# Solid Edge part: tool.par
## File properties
Author: Romil
Template: Iso Part.par
Last saved by: Romil
Revision: 19
Application: Solid Edge
Accuracy: 0.990
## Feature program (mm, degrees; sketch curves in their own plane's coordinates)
sketch for "unnamed Protrusion 1" plane through (0, 0, 0) normal (0, 0, 1) x-axis (1, 0, 0)
  line (23.8, 7.9) -> (23.8, -7.9)
  line (23.8, -7.9) -> (0, -7.9)
  line (0, -7.9) -> (0, 7.9)
  line (0, 7.9) -> (23.8, 7.9)
extrude "unnamed Protrusion 1" add finite 18.2 along +normal
sketch for "ExtrudedProtrusion_2" plane through (0, 0, 0) normal (0, -1, 0) x-axis (1, 0, 0)
  line (-1.8655, 31.7221) -> (-0.9815, 27.8216)
  arc centre (-0.884, 27.8437) radius 0.1 from (-0.9815, 27.8216) to (-0.963, 27.7825) ccw
  line (-0.963, 27.7825) -> (8.4676, 15.6125)
  arc centre (7.6771, 15) radius 1 from (7.6771, 14) to (8.4676, 15.6125) ccw
  line (7.6771, 14) -> (2.1511, 14)
  line (2.1511, 14) -> (2.5591, 12.2)
  line (11.5232, 12.2) -> (2.5591, 12.2)
  line (11.5232, 12.2) -> (20.6599, 12.2)
  arc centre (20.6599, 10.7) radius 1.5 from (20.6599, 12.2) to (22.1051, 11.1015) cw
  line (23.8, 5) -> (22.1051, 11.1015)
  line (23.8, 1.8) -> (23.8, 5)
  line (3.7179, 1.8) -> (23.8, 1.8)
  line (3.7179, 1.8) -> (-3.0555, 31.6779)
  arc centre (-2.958, 31.7) radius 0.1 from (-3.0555, 31.6779) to (-2.958, 31.8) cw
  line (-2.958, 31.8) -> (-1.963, 31.8)
  arc centre (-1.963, 31.7) radius 0.1 from (-1.8655, 31.7221) to (-1.963, 31.8) ccw
extrude "ExtrudedProtrusion_2" add finite 31.8 symmetric
sketch for "ExtrudedCutout_1" #1 plane through (0, 0, 0) normal (1, 0, 0) x-axis (0, 1, 0)
  line (-22.2684, 12.2) -> (-22.2684, 36.765)
  line (-22.2684, 36.765) -> (-15.9, 36.198)
  line (-15.9, 36.198) -> (-9.2, 36.198)
  line (-9.2, 36.198) -> (-9.2, 12.2)
  line (-9.2, 12.2) -> (-22.2684, 12.2)
sketch for "ExtrudedCutout_1" #2 plane through (0, 0, 0) normal (1, 0, 0) x-axis (0, 1, 0)
  line (15.9, 36.198) -> (9.2, 36.198)
  line (9.2, 36.198) -> (9.2, 12.2)
  line (9.2, 12.2) -> (22.2684, 12.2)
  line (22.2684, 12.2) -> (22.2684, 36.765)
  line (22.2684, 36.765) -> (15.9, 36.198)
extrude "ExtrudedCutout_1" cut finite 113.7012 symmetric
sketch for "unnamed Cutout 1" plane through (0, -35.2373, 0) normal (0, -1, 0) x-axis (1, 0, 0)
  line (0, 0) -> (0, 0)
  line (-0.963, 27.7825) -> (20.7421, 27.7825)
  line (20.7421, 27.7825) -> (26.4702, 27.7825)
  line (26.4702, 27.7825) -> (25.9334, 3)
  line (6.641, 3) -> (25.9334, 3)
  arc centre (6.641, 5.5) radius 2.5 from (4.2028, 4.9474) to (6.641, 3) ccw
  line (2.1511, 14) -> (4.2028, 4.9474)
  line (2.1511, 14) -> (7.6771, 14)
  arc centre (7.6771, 15) radius 1 from (7.6771, 14) to (8.4676, 15.6125) ccw
  line (-0.963, 27.7825) -> (8.4676, 15.6125)
extrude "unnamed Cutout 1" cut along -normal
sketch for "unnamed Cutout 2" plane through (0, -35.2373, 0) normal (0, -1, 0) x-axis (1, 0, 0)
  line (11.8926, 5.5) -> (6.5536, 5.5)
  arc centre (6.5536, 8.6) radius 3.1 from (6.5536, 5.5) to (3.5303, 7.9148) cw
  line (2.1511, 14) -> (3.5303, 7.9148)
  line (2.1511, 14) -> (7.6771, 14)
  line (10.977, 14) -> (7.6771, 14)
  line (17.8766, 15.3192) -> (10.977, 14)
  line (17.8766, 5.5) -> (17.8766, 15.3192)
  line (11.8926, 5.5) -> (17.8766, 5.5)
extrude "unnamed Cutout 2" cut along -normal
sketch for "unnamed Cutout 3" plane through (0, -35.2373, 0) normal (0, -1, 0) x-axis (1, 0, 0)
  line (17.8766, 5.5) -> (17.8766, 15.3192)
  line (17.8766, 15.3192) -> (10.977, 14)
  line (10.977, 14) -> (7.6771, 14)
  line (2.1511, 14) -> (7.6771, 14)
  line (2.1511, 14) -> (3.5303, 7.9148)
  arc centre (6.5536, 8.6) radius 3.1 from (6.5536, 5.5) to (3.5303, 7.9148) cw
  line (11.8926, 5.5) -> (6.5536, 5.5)
  line (11.8926, 5.5) -> (17.8766, 5.5)
extrude "unnamed Cutout 3" cut along -normal
sketch for "unnamed Cutout 4" plane through (0, -35.2373, 0) normal (0, -1, 0) x-axis (1, 0, 0)
  line (-0.3297, 5) -> (-0.3297, 0)
  line (-0.3297, 0) -> (26.2671, 0)
  line (26.2671, 0) -> (26.2671, 5)
  line (7.3837, 5) -> (26.2671, 5)
  line (7.3837, 5) -> (-0.3297, 5)
extrude "unnamed Cutout 4" cut along -normal
sketch for "unnamed Cutout 5" plane through (0, -35.2373, 0) normal (0, -1, 0) x-axis (1, 0, 0)
  line (7.3837, 5) -> (-0.3297, 5)
  line (-0.3297, 5) -> (-0.3297, 0)
  line (-0.3297, 0) -> (26.2671, 0)
  line (26.2671, 0) -> (26.2671, 5)
  line (7.3837, 5) -> (26.2671, 5)
extrude "unnamed Cutout 5" cut along -normal
sketch for "unnamed Cutout 6" plane through (0, 0, 0) normal (1, 0, 0) x-axis (0, 1, 0)
  line (8.6, 29.1117) -> (-8.6, 29.1117)
  line (-8.6, 29.1117) -> (-8.6, 9.0802)
  line (-8.6, 9.0802) -> (8.6, 9.0802)
  line (8.6, 9.0802) -> (8.6, 29.1117)
extrude "unnamed Cutout 6" cut along +normal
sketch for "ExtrudedCutout_19" #1 plane through (0, 0, 0) normal (0, -1, 0) x-axis (1, 0, 0)
  circle centre (14.5536, 8.6) radius 2.4
sketch for "ExtrudedCutout_19" #2 plane through (0, 0, 0) normal (0, -1, 0) x-axis (1, 0, 0)
  circle centre (6.5536, 8.6) radius 2.4
extrude "ExtrudedCutout_19" cut finite 58.1345 symmetric
fillet "Round_1" radius 0.9
sketch for "ExtrudedCutout_20" #1 plane through (12.5801, -15.9, 8.6) normal (0, -1, 0) x-axis (1, 0, 0)
  circle centre (1.9735, 0) radius 3.1
sketch for "ExtrudedCutout_20" #2 plane through (12.5801, -15.9, 8.6) normal (0, -1, 0) x-axis (1, 0, 0)
  circle centre (-6.0265, 0) radius 3.1
extrude "ExtrudedCutout_20" cut finite 0.9 along -normal
sketch for "unnamed Cutout 7" plane through (-13.9505, 0, 0) normal (1, 0, 0) x-axis (0, 1, 0)
  line (-6.7, 12.4028) -> (-6.7, 17)
  line (-6.7, 17) -> (-4.9951, 17)
  line (5.4564, 17) -> (-4.9951, 17)
  line (6.7, 17) -> (5.4564, 17)
  line (6.7, 12.4028) -> (6.7, 17)
  line (6.7, 12.4028) -> (6.7, 7.9566)
  line (6.7, 7.9566) -> (6.7, 5)
  line (6.7, 3.8) -> (6.7, 5)
  line (4.455, 3.8) -> (6.7, 3.8)
  line (4.455, 4.4) -> (4.455, 3.8)
  line (4.455, 4.4) -> (4.455, 5)
  line (4.455, 5) -> (3.255, 5)
  line (3.255, 5) -> (3.255, 3.8)
  line (3.255, 3.8) -> (-3.255, 3.8)
  line (-3.255, 5) -> (-3.255, 3.8)
  line (-3.255, 5) -> (-4.455, 5)
  line (-4.455, 4.4) -> (-4.455, 5)
  line (-4.455, 4.4) -> (-4.455, 3.8)
  line (-4.455, 3.8) -> (-6.7, 3.8)
  line (-6.7, 3.8) -> (-6.7, 5)
  line (-6.7, 12.4028) -> (-6.7, 5)
extrude "unnamed Cutout 7" cut along +normal
logasc func "Lip_Groove_4"  LipOrGrooveWidth = 1 mm; LipOrGrooveHeight = 1 mm
logasc func "Lip_Groove_5"  LipOrGrooveWidth = 1 mm; LipOrGrooveHeight = 2 mm
logasc func "Lip_Groove_6"  LipOrGrooveWidth = 1 mm; LipOrGrooveHeight = 1 mm
logasc func "Lip_Groove_7"  LipOrGrooveWidth = 1 mm; LipOrGrooveHeight = 1 mm
logasc func "Lip_Groove_8"  LipOrGrooveWidth = 1 mm; LipOrGrooveHeight = 1 mm
mirror "unnamed Mirror 1" of "ExtrudedCutout_20", "Lip_Groove_4", "Lip_Groove_7", "Lip_Groove_6" about plane through (0, 0, 0) normal (0, -1, 0)
extrude "unnamed Cutout 8" cut finite 0.9
logasc func "unnamed LOGAscFunc 1"
logasc func "unnamed LOGAscFunc 2"
logasc func "unnamed LOGAscFunc 3"
logasc func "Lip_Groove_17"  LipOrGrooveWidth = 1 mm; LipOrGrooveHeight = 2 mm
logasc func "Lip_Groove_18"  LipOrGrooveWidth = 1 mm; LipOrGrooveHeight = 1 mm
sketch for "ExtrudedCutout_22" plane through (11.9, 0, 0) normal (0, 0, -1) x-axis (0, -1, 0)
  line (-7.3, 11.3) -> (-7.3, -11.3)
  line (-7.3, -11.3) -> (7.3, -11.3)
  line (7.3, -11.3) -> (7.3, 11.3)
  line (7.3, 11.3) -> (-7.3, 11.3)
extrude "ExtrudedCutout_22" cut finite 2 along -normal
sketch for "unnamed Protrusion 2" #1 plane through (11.9, 0, 0) normal (0, 0, -1) x-axis (0, -1, 0)
  circle centre (0, 4) radius 3.255
sketch for "unnamed Protrusion 2" #2 plane through (11.9, 0, 0) normal (0, 0, -1) x-axis (0, -1, 0)
  circle centre (0, -4) radius 3.255
extrude "unnamed Protrusion 2" add to key point along -normal
sketch for "unnamed Cutout 9" #1 plane through (11.9, 0, 0) normal (0, 0, -1) x-axis (0, -1, 0)
  circle centre (0, 4) radius 2.4
sketch for "unnamed Cutout 9" #2 plane through (11.9, 0, 0) normal (0, 0, -1) x-axis (0, -1, 0)
  circle centre (0, -4) radius 2.4
extrude "unnamed Cutout 9" cut to key point along -normal
sketch for "unnamed Protrusion 3" plane through (-13.9505, 0, 0) normal (1, 0, 0) x-axis (0, 1, 0)
  circle centre (0, 11) radius 3.255
extrude "unnamed Protrusion 3" add along +normal
sketch for "unnamed Cutout 10" plane through (-13.9505, 0, 0) normal (1, 0, 0) x-axis (0, 1, 0)
  circle centre (0, 11) radius 2.4
extrude "unnamed Cutout 10" cut along +normal
Other named dimensions: "ExtrudedSurface_2": FiniteDepth = 91.0685 mm | "ExtrudedSurface_3": FiniteDepth = 436.5734 mm | "ExtrudedSurface_6": FiniteDepth = 1375.4947 mm | "ExtrudedSurface_7": FiniteDepth = 1208.2439 mm | "OffsetSurface_2": Distance = 1.2 mm | "OffsetSurface_3": Distance = 1.2 mm | "ExtrudedSurface_8": FiniteDepth = 76.2865 mm | "ExtrudedSurface_9": FiniteDepth = 140.5724 mm
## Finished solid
Body 1: sheet body, 5 faces, 16 edges, 12 vertices.
  Faces by surface: plane 4, cylinder 1
  Edges by curve: line 14, circle 2
Body 2: sheet body, 1 face, 4 edges, 4 vertices.
  Faces by surface: plane 1
  Edges by curve: line 4
Body 3: sheet body, 3 faces, 10 edges, 8 vertices.
  Faces by surface: plane 2, cylinder 1
  Edges by curve: line 8, circle 2
Body 4: sheet body, 3 faces, 10 edges, 8 vertices.
  Faces by surface: plane 2, cylinder 1
  Edges by curve: line 8, circle 2
Body 5: sheet body, 3 faces, 10 edges, 8 vertices.
  Faces by surface: plane 2, cylinder 1
  Edges by curve: line 8, circle 2
Body 6: sheet body, 3 faces, 10 edges, 8 vertices.
  Faces by surface: plane 2, cylinder 1
  Edges by curve: line 8, circle 2
Body 7: sheet body, 3 faces, 10 edges, 8 vertices.
  Faces by surface: plane 2, cylinder 1
  Edges by curve: line 8, circle 2
Body 8: sheet body, 3 faces, 10 edges, 8 vertices.
  Faces by surface: plane 2, cylinder 1
  Edges by curve: line 8, circle 2
Body 9: solid body, 137 faces, 341 edges, 204 vertices.
  Faces by surface: plane 93, cylinder 38, blend 2, sphere 2, torus 2
  Edges by curve: line 243, circle 76, ellipse 14, intersection 8
Bounding box of the edges (mm; curved faces can reach further): 54.570 x 140.572 x 1375.495, from (-19.3884, -70.2862, -687.7474) to (35.1817, 70.2862, 687.7474).
Cylindrical faces by radius (mm): R0.1 x4, R0.2 x4, R0.9 x4, R1 x2, R1.5 x2, R2.4 x7, R2.5 x5, R3.1 x6, R3.255 x3, R71.1117 x4, R72.3117 x4
Toroidal faces (ring radius, tube radius in mm): R72.0117 r0.9 x2
Spherical faces by radius (mm): R0.9 x2
Planar faces by outward normal: +x 2, +y 17, +z 15, -x 4, -y 18, -z 19, oblique 18
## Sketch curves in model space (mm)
line (25.3334, 0, 3) -> (25.3334, 0, -11.652)
line (1.1859, 0, 33.233) -> (1.1859, 0, 15.6113)
line (1.1859, 0, 15.6113) -> (3.6028, 0, 4.9474)
arc centre (6.041, 0, 5.5) radius 2.5 from (3.6028, 0, 4.9474) through (4.5387, 0, 3.5017) to (6.041, 0, 3)
line (6.041, 0, 3) -> (25.3334, 0, 3)
circle centre (-13.9505, 0, 11) radius 3.255
circle centre (-13.9505, 0, 11) radius 2.4
line (-13.9505, -6.7, 17) -> (-13.9505, -4.9951, 17)
line (-13.9505, -6.7, 12.4028) -> (-13.9505, -6.7, 17)
line (-13.9505, -6.7, 12.4028) -> (-13.9505, -6.7, 5)
line (-13.9505, -6.7, 3.8) -> (-13.9505, -6.7, 5)
line (-13.9505, -4.455, 3.8) -> (-13.9505, -6.7, 3.8)
line (-13.9505, -4.455, 4.4) -> (-13.9505, -4.455, 3.8)
line (-13.9505, -4.455, 4.4) -> (-13.9505, -4.455, 5)
line (-13.9505, -3.255, 5) -> (-13.9505, -4.455, 5)
line (-13.9505, -3.255, 5) -> (-13.9505, -3.255, 3.8)
line (-13.9505, 3.255, 3.8) -> (-13.9505, -3.255, 3.8)
line (-13.9505, 3.255, 5) -> (-13.9505, 3.255, 3.8)
line (-13.9505, 4.455, 5) -> (-13.9505, 3.255, 5)
line (-13.9505, 4.455, 4.4) -> (-13.9505, 4.455, 5)
line (-13.9505, 4.455, 4.4) -> (-13.9505, 4.455, 3.8)
line (-13.9505, 4.455, 3.8) -> (-13.9505, 6.7, 3.8)
line (-13.9505, 6.7, 3.8) -> (-13.9505, 6.7, 5)
line (-13.9505, 6.7, 7.9566) -> (-13.9505, 6.7, 5)
line (-13.9505, 6.7, 12.4028) -> (-13.9505, 6.7, 7.9566)
line (-13.9505, 6.7, 12.4028) -> (-13.9505, 6.7, 17)
line (-13.9505, 6.7, 17) -> (-13.9505, 5.4564, 17)
line (-13.9505, 5.4564, 17) -> (-13.9505, -4.9951, 17)
circle centre (7.9, 0, 0) radius 3.255
circle centre (15.9, 0, 0) radius 3.255
circle centre (15.9, 0, 0) radius 2.4
circle centre (7.9, 0, 0) radius 2.4
line (23.2, -7.3, 0) -> (0.6, -7.3, 0)
line (0.6, -7.3, 0) -> (0.6, 7.3, 0)
line (0.6, 7.3, 0) -> (23.2, 7.3, 0)
line (23.2, 7.3, 0) -> (23.2, -7.3, 0)
circle centre (14.5536, -15.9, 8.6) radius 3.1
circle centre (6.5536, -15.9, 8.6) radius 3.1
circle centre (14.5536, 0, 8.6) radius 3.1
circle centre (14.5536, 0, 8.6) radius 2.4
circle centre (6.5536, 0, 8.6) radius 2.4
circle centre (6.5536, 0, 8.6) radius 3.1
circle centre (6.5536, 0, 8.6) radius 3.1
line (0, 8.6, 9.0802) -> (0, 8.6, 29.1117)
line (0, 8.6, 29.1117) -> (0, -8.6, 29.1117)
line (0, -8.6, 29.1117) -> (0, -8.6, 9.0802)
line (0, -8.6, 9.0802) -> (0, 8.6, 9.0802)
line (-2.0802, 0, 32.6694) -> (6.7206, 0, -6.1618)
line (17.8766, -35.2373, 5.5) -> (17.8766, -35.2373, 15.3192)
line (17.8766, -35.2373, 15.3192) -> (10.977, -35.2373, 14)
line (10.977, -35.2373, 14) -> (7.6771, -35.2373, 14)
line (2.1511, -35.2373, 14) -> (7.6771, -35.2373, 14)
line (2.1511, -35.2373, 14) -> (3.5303, -35.2373, 7.9148)
arc centre (6.5536, -35.2373, 8.6) radius 3.1 from (6.5536, -35.2373, 5.5) through (4.5488, -35.2373, 6.2355) to (3.5303, -35.2373, 7.9148)
line (11.8926, -35.2373, 5.5) -> (6.5536, -35.2373, 5.5)
line (11.8926, -35.2373, 5.5) -> (17.8766, -35.2373, 5.5)
arc centre (7.6771, -35.2373, 15) radius 1 from (7.6771, -35.2373, 14) through (8.575, -35.2373, 14.5598) to (8.4676, -35.2373, 15.6125)
line (2.1511, -35.2373, 14) -> (7.6771, -35.2373, 14)
line (2.1511, -35.2373, 14) -> (4.2028, -35.2373, 4.9474)
arc centre (6.641, -35.2373, 5.5) radius 2.5 from (4.2028, -35.2373, 4.9474) through (5.1387, -35.2373, 3.5017) to (6.641, -35.2373, 3)
line (6.641, -35.2373, 3) -> (25.9334, -35.2373, 3)
line (26.4702, -35.2373, 27.7825) -> (25.9334, -35.2373, 3)
line (20.7421, -35.2373, 27.7825) -> (26.4702, -35.2373, 27.7825)
line (-0.963, -35.2373, 27.7825) -> (20.7421, -35.2373, 27.7825)
line (-0.963, -35.2373, 27.7825) -> (8.4676, -35.2373, 15.6125)
line (0, 7.9, 0) -> (-19.3884, 7.9, 0)
arc centre (0, 80.2117, 0) radius 72.3117 from (0, 7.9, 0) through (6.0339, 8.1522, 0) to (12.0257, 8.907, 0)
line (35.1817, 15.1866, 0) -> (12.0257, 8.907, 0)
line (0, -7.9, 0) -> (-17.2765, -7.9, 0)
arc centre (0, -80.2117, 0) radius 72.3117 from (0, -7.9, 0) through (6.0339, -8.1522, 0) to (12.0257, -8.907, 0)
line (35.1817, -15.1866, 0) -> (12.0257, -8.907, 0)
line (26.2671, -35.2373, 0) -> (26.2671, -35.2373, 5)
line (-0.3297, -35.2373, 0) -> (26.2671, -35.2373, 0)
line (-0.3297, -35.2373, 5) -> (-0.3297, -35.2373, 0)
line (7.3837, -35.2373, 5) -> (-0.3297, -35.2373, 5)
line (7.3837, -35.2373, 5) -> (26.2671, -35.2373, 5)
arc centre (6.641, -35.2373, 5.5) radius 2.5 from (4.2028, -35.2373, 4.9474) through (5.1387, -35.2373, 3.5017) to (6.641, -35.2373, 3)
line (6.641, -35.2373, 3) -> (25.9334, -35.2373, 3)
line (26.4702, -35.2373, 27.7825) -> (25.9334, -35.2373, 3)
line (20.7421, -35.2373, 27.7825) -> (26.4702, -35.2373, 27.7825)
line (-0.963, -35.2373, 27.7825) -> (20.7421, -35.2373, 27.7825)
line (-0.963, -35.2373, 27.7825) -> (8.4676, -35.2373, 15.6125)
arc centre (7.6771, -35.2373, 15) radius 1 from (7.6771, -35.2373, 14) through (8.575, -35.2373, 14.5598) to (8.4676, -35.2373, 15.6125)
line (2.1511, -35.2373, 14) -> (7.6771, -35.2373, 14)
line (2.1511, -35.2373, 14) -> (4.2028, -35.2373, 4.9474)
arc centre (6.5536, -35.2373, 8.6) radius 3.1 from (6.5536, -35.2373, 5.5) through (4.5488, -35.2373, 6.2355) to (3.5303, -35.2373, 7.9148)
line (11.8926, -35.2373, 5.5) -> (25.9876, -35.2373, 5.5)
line (11.8926, -35.2373, 5.5) -> (6.5536, -35.2373, 5.5)
arc centre (23.6, -12.253, 0) radius 0.2 from (23.8, -12.253, 0) through (23.7589, -12.1315, 0) to (23.6523, -12.06, 0)
line (35.1817, -15.1866, 0) -> (12.0257, -8.907, 0)
arc centre (11.9734, -9.1, 0) radius 0.2 from (11.9734, -8.9, 0) through (11.9998, -8.9018, 0) to (12.0257, -8.907, 0)
line (8, -8.9, 0) -> (11.9734, -8.9, 0)
line (0, -8.9, 0) -> (-16.7142, -8.9, 0)
line (0, -8.9, 0) -> (8, -8.9, 0)
line (35.1817, 15.1866, 0) -> (12.0257, 8.907, 0)
arc centre (11.9734, 9.1, 0) radius 0.2 from (11.9734, 8.9, 0) through (11.9998, 8.9018, 0) to (12.0257, 8.907, 0)
line (8, 8.9, 0) -> (11.9734, 8.9, 0)
line (0, 8.9, 0) -> (-16.7142, 8.9, 0)
line (0, 8.9, 0) -> (8, 8.9, 0)
line (0, -9.2, 31.8637) -> (0, 9.2, 31.8637)
line (0, -9.2, 36.198) -> (0, -9.2, 12.2)
line (0, -9.2, 12.2) -> (0, -22.2684, 12.2)
line (0, -22.2684, 12.2) -> (0, -22.2684, 36.765)
line (0, -22.2684, 36.765) -> (0, -15.9, 36.198)
line (0, -15.9, 36.198) -> (0, -9.2, 36.198)
line (0, 9.2, 36.198) -> (0, 9.2, 12.2)
line (0, 9.2, 12.2) -> (0, 22.2684, 12.2)
line (0, 22.2684, 12.2) -> (0, 22.2684, 36.765)
line (0, 22.2684, 36.765) -> (0, 15.9, 36.198)
line (0, 15.9, 36.198) -> (0, 9.2, 36.198)
line (23.8, 0, 5) -> (22.1051, 0, 11.1015)
arc centre (20.6599, 0, 10.7) radius 1.5 from (20.6599, 0, 12.2) through (21.5676, 0, 11.8942) to (22.1051, 0, 11.1015)
line (11.5232, 0, 12.2) -> (20.6599, 0, 12.2)
line (11.5232, 0, 12.2) -> (2.5591, 0, 12.2)
line (2.1511, 0, 14) -> (2.5591, 0, 12.2)
line (7.6771, 0, 14) -> (2.1511, 0, 14)
arc centre (7.6771, 0, 15) radius 1 from (7.6771, 0, 14) through (8.575, 0, 14.5598) to (8.4676, 0, 15.6125)
line (-0.963, 0, 27.7825) -> (8.4676, 0, 15.6125)
arc centre (-0.884, 0, 27.8437) radius 0.1 from (-0.9815, 0, 27.8216) through (-0.9744, 0, 27.801) to (-0.963, 0, 27.7825)
line (-1.8655, 0, 31.7221) -> (-0.9815, 0, 27.8216)
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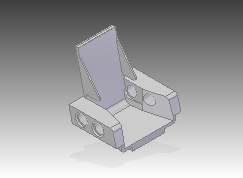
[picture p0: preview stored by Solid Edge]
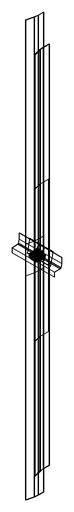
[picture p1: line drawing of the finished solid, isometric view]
